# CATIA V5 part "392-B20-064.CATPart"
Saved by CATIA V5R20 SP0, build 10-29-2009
Part number: 392-B20-064
Definition: NONE
Nomenclature: 392-B20-064
Source: Unknown
Description: 392-B20-064
Bounding box of the stored display mesh (mm): x 0 to 64, y -9.277 to 9.277, z -9.2 to 9.2
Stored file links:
  C:\Users\Utente\Desktop\IO LAVORO\3D X SITO CF\X SITO\3D files 392B\392-B20-064.CATPart
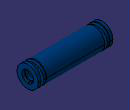
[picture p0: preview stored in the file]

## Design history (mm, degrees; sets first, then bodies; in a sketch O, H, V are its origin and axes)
Body1 "392-B20-064" (main body)
  Solid1: solid without history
